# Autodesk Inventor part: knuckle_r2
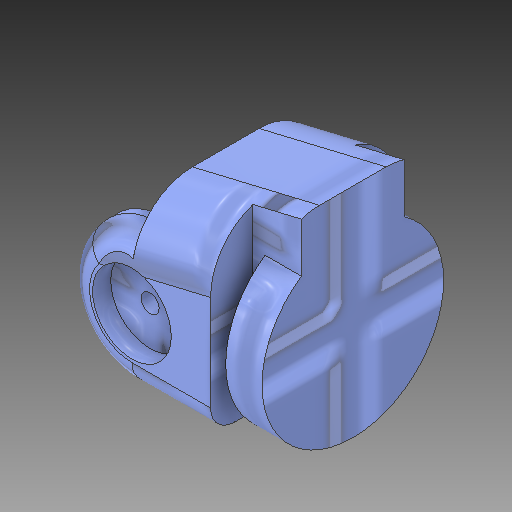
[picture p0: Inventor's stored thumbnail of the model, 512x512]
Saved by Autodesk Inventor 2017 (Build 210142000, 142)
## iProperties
Created: 2017-05
Part Number: knuckle_r2
Material: Generic
Document SubType Name: Modeling
Designer: alez_
Density: 1 g/cm^3
Appearance: Default
Author: alez_
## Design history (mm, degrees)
derived "knuckle.ipt" dims "d0" = 11
feature "Solid1::knuckle.ipt" dims "d0" = 11
tag "TaggingFeature1"
body "Solid1"
